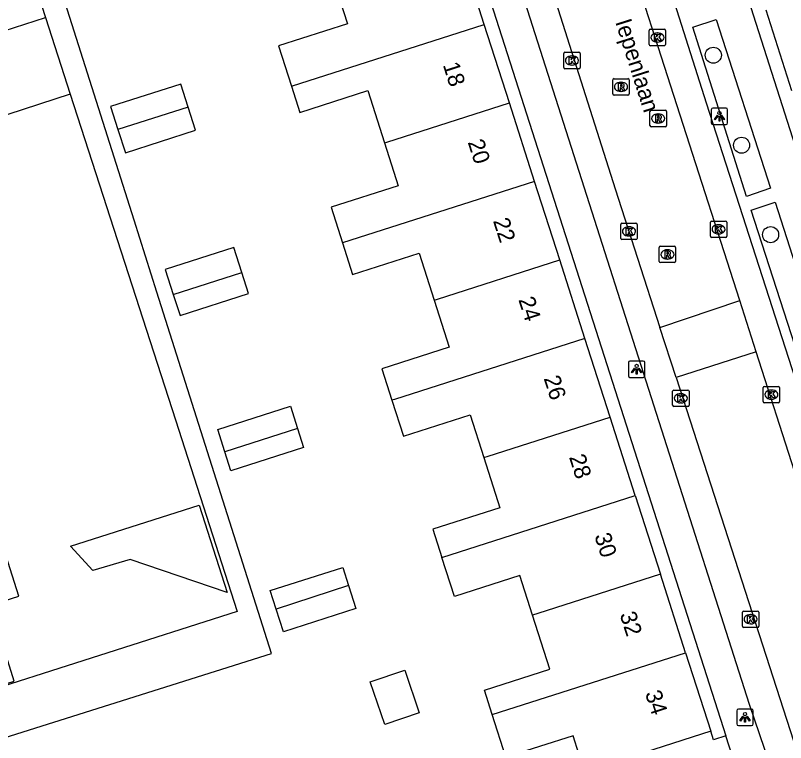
# Model space of a CAD drawing. Extents: x 159718 to 160783, y 383290 to 384030.
# Drawn here: x 160111.85 to 160158.8, y 383596.25 to 383640.55 of the extents above; entities that cross this region are included whole.
import ezdxf

# ---------------------------------------------------------------- set-up
doc = ezdxf.new("R2010")
doc.units = 0
for name, color, linetype in [('IMGEO_Boom', 7, 'Continuous'), ('IMGEO_Kolk', 7, 'Continuous'), ('IMGEO_Lichtpunt', 7, 'Continuous'), ('IMGEO_Openbare_ruimte_label', 7, 'Continuous'), ('IMGEO_Pand', 7, 'Continuous'), ('IMGEO_Pand_nummerreeks', 7, 'Continuous'), ('IMGEO_Rijbaan_lokaal_open', 7, 'Continuous'), ('IMGEO_Rioolput', 7, 'Continuous'), ('IMGEO_Voetpad_open', 7, 'Continuous')]:
    doc.layers.add(name, color=color, linetype=linetype)

msp = doc.modelspace()

# ---------------------------------------------------------------- linework, layer by layer
at = {"layer": 'IMGEO_Boom'}
for centre in [(160154.395, 383638.127), (160156.119, 383632.642), (160157.889, 383627.194)]:
    msp.add_circle(centre, 0.489, dxfattribs=at)
at = {"layer": 'IMGEO_Kolk'}
for p, q in [((160150.488, 383638.781), (160150.488, 383639.633)), ((160150.563, 383639.707), (160151.415, 383639.707)), ((160150.976, 383639.487), (160151.001, 383639.487)), ((160151.489, 383639.633), (160151.489, 383638.781)), ((160150.999, 383638.927), (160150.974, 383638.927)), ((160151.415, 383638.707), (160150.563, 383638.707)), ((160145.277, 383637.379), (160145.277, 383638.231)), ((160145.352, 383638.305), (160146.204, 383638.305)), ((160145.765, 383638.085), (160145.79, 383638.085)), ((160146.278, 383638.231), (160146.278, 383637.379)), ((160145.788, 383637.525), (160145.763, 383637.525)), ((160146.204, 383637.305), (160145.352, 383637.305)), ((160154.29, 383628.02), (160155.142, 383628.02)), ((160148.752, 383626.967), (160148.752, 383627.819)), ((160148.827, 383627.893), (160149.679, 383627.893)), ((160149.24, 383627.673), (160149.265, 383627.673)), ((160149.753, 383627.819), (160149.753, 383626.967)), ((160154.215, 383627.094), (160154.215, 383627.946)), ((160154.703, 383627.8), (160154.728, 383627.8)), ((160155.216, 383627.946), (160155.216, 383627.094)), ((160149.263, 383627.113), (160149.238, 383627.113)), ((160154.726, 383627.24), (160154.701, 383627.24)), ((160149.679, 383626.893), (160148.827, 383626.893)), ((160155.142, 383627.02), (160154.29, 383627.02)), ((160151.991, 383617.725), (160152.843, 383617.725)), ((160157.435, 383617.023), (160157.435, 383617.875)), ((160157.51, 383617.949), (160158.362, 383617.949)), ((160157.923, 383617.729), (160157.948, 383617.729)), ((160158.436, 383617.875), (160158.436, 383617.023)), ((160151.916, 383616.799), (160151.916, 383617.651)), ((160152.404, 383617.505), (160152.429, 383617.505)), ((160152.917, 383617.651), (160152.917, 383616.799)), ((160152.427, 383616.945), (160152.402, 383616.945)), ((160158.362, 383616.949), (160157.51, 383616.949)), ((160157.946, 383617.169), (160157.921, 383617.169)), ((160152.843, 383616.725), (160151.991, 383616.725)), ((160156.166, 383603.339), (160156.166, 383604.191)), ((160156.241, 383604.265), (160157.093, 383604.265)), ((160157.167, 383604.191), (160157.167, 383603.339)), ((160156.654, 383604.045), (160156.679, 383604.045)), ((160157.093, 383603.265), (160156.241, 383603.265)), ((160156.677, 383603.485), (160156.652, 383603.485))]:
    msp.add_line(p, q, dxfattribs=at)
for points in [[(160150.488, 383638.781), (160150.488, 383639.633)], [(160150.563, 383639.707), (160151.415, 383639.707)], [(160150.809, 383639.407), (160150.932, 383639.407), (160150.932, 383639.256), (160151.062, 383639.407), (160151.226, 383639.407), (160151.08, 383639.256), (160151.233, 383639.007), (160151.081, 383639.007), (160150.996, 383639.171), (160150.932, 383639.104), (160150.932, 383639.007), (160150.809, 383639.007), (160150.809, 383639.407)], [(160151.489, 383639.633), (160151.489, 383638.781)], [(160151.415, 383638.707), (160150.563, 383638.707)], [(160145.277, 383637.379), (160145.277, 383638.231)], [(160145.352, 383638.305), (160146.204, 383638.305)], [(160145.598, 383638.005), (160145.721, 383638.005), (160145.721, 383637.854), (160145.851, 383638.005), (160146.015, 383638.005), (160145.869, 383637.854), (160146.022, 383637.605), (160145.87, 383637.605), (160145.785, 383637.769), (160145.721, 383637.702), (160145.721, 383637.605), (160145.598, 383637.605), (160145.598, 383638.005)], [(160146.278, 383638.231), (160146.278, 383637.379)], [(160146.204, 383637.305), (160145.352, 383637.305)], [(160154.29, 383628.02), (160155.142, 383628.02)], [(160148.752, 383626.967), (160148.752, 383627.819)], [(160148.827, 383627.893), (160149.679, 383627.893)], [(160149.073, 383627.593), (160149.196, 383627.593), (160149.196, 383627.442), (160149.326, 383627.593), (160149.49, 383627.593), (160149.344, 383627.442), (160149.497, 383627.193), (160149.345, 383627.193), (160149.26, 383627.357), (160149.196, 383627.29), (160149.196, 383627.193), (160149.073, 383627.193), (160149.073, 383627.593)], [(160149.753, 383627.819), (160149.753, 383626.967)], [(160154.215, 383627.094), (160154.215, 383627.946)], [(160154.536, 383627.72), (160154.659, 383627.72), (160154.659, 383627.569), (160154.789, 383627.72), (160154.953, 383627.72), (160154.807, 383627.569), (160154.96, 383627.32), (160154.808, 383627.32), (160154.723, 383627.484), (160154.659, 383627.417), (160154.659, 383627.32), (160154.536, 383627.32), (160154.536, 383627.72)], [(160155.216, 383627.946), (160155.216, 383627.094)], [(160149.679, 383626.893), (160148.827, 383626.893)], [(160155.142, 383627.02), (160154.29, 383627.02)], [(160151.991, 383617.725), (160152.843, 383617.725)], [(160157.435, 383617.023), (160157.435, 383617.875)], [(160157.51, 383617.949), (160158.362, 383617.949)], [(160158.436, 383617.875), (160158.436, 383617.023)], [(160151.916, 383616.799), (160151.916, 383617.651)], [(160152.237, 383617.425), (160152.36, 383617.425), (160152.36, 383617.274), (160152.49, 383617.425), (160152.654, 383617.425), (160152.508, 383617.274), (160152.661, 383617.025), (160152.509, 383617.025), (160152.424, 383617.189), (160152.36, 383617.122), (160152.36, 383617.025), (160152.237, 383617.025), (160152.237, 383617.425)], [(160152.917, 383617.651), (160152.917, 383616.799)], [(160157.756, 383617.649), (160157.879, 383617.649), (160157.879, 383617.498), (160158.009, 383617.649), (160158.173, 383617.649), (160158.027, 383617.498), (160158.18, 383617.249), (160158.028, 383617.249), (160157.943, 383617.413), (160157.879, 383617.346), (160157.879, 383617.249), (160157.756, 383617.249), (160157.756, 383617.649)], [(160158.362, 383616.949), (160157.51, 383616.949)], [(160152.843, 383616.725), (160151.991, 383616.725)], [(160156.166, 383603.339), (160156.166, 383604.191)], [(160156.241, 383604.265), (160157.093, 383604.265)], [(160157.167, 383604.191), (160157.167, 383603.339)], [(160156.487, 383603.965), (160156.61, 383603.965), (160156.61, 383603.814), (160156.74, 383603.965), (160156.904, 383603.965), (160156.758, 383603.814), (160156.911, 383603.565), (160156.759, 383603.565), (160156.674, 383603.729), (160156.61, 383603.662), (160156.61, 383603.565), (160156.487, 383603.565), (160156.487, 383603.965)], [(160157.093, 383603.265), (160156.241, 383603.265)]]:
    msp.add_lwpolyline(points, dxfattribs=at)
for centre, start, end in [((160150.565, 383639.631), 91.552, 178.448), ((160150.565, 383639.631), 91.552, 178.448), ((160151.413, 383639.631), 1.552, 88.448), ((160151.413, 383639.631), 1.552, 88.448), ((160150.565, 383638.783), 181.552, 268.448), ((160150.565, 383638.783), 181.552, 268.448), ((160151.413, 383638.783), 271.552, 358.448), ((160151.413, 383638.783), 271.552, 358.448), ((160145.354, 383638.229), 91.552, 178.448), ((160145.354, 383638.229), 91.552, 178.448), ((160146.202, 383638.229), 1.552, 88.448), ((160146.202, 383638.229), 1.552, 88.448), ((160145.354, 383637.381), 181.552, 268.448), ((160145.354, 383637.381), 181.552, 268.448), ((160146.202, 383637.381), 271.552, 358.448), ((160146.202, 383637.381), 271.552, 358.448), ((160154.292, 383627.944), 91.552, 178.448), ((160154.292, 383627.944), 91.552, 178.448), ((160155.14, 383627.944), 1.552, 88.448), ((160155.14, 383627.944), 1.552, 88.448), ((160148.829, 383627.817), 91.552, 178.448), ((160148.829, 383627.817), 91.552, 178.448), ((160149.677, 383627.817), 1.552, 88.448), ((160149.677, 383627.817), 1.552, 88.448), ((160154.292, 383627.096), 181.552, 268.448), ((160154.292, 383627.096), 181.552, 268.448), ((160155.14, 383627.096), 271.552, 358.448), ((160155.14, 383627.096), 271.552, 358.448), ((160148.829, 383626.969), 181.552, 268.448), ((160148.829, 383626.969), 181.552, 268.448), ((160149.677, 383626.969), 271.552, 358.448), ((160149.677, 383626.969), 271.552, 358.448), ((160151.993, 383617.649), 91.552, 178.448), ((160151.993, 383617.649), 91.552, 178.448), ((160152.841, 383617.649), 1.552, 88.448), ((160152.841, 383617.649), 1.552, 88.448), ((160157.512, 383617.873), 91.552, 178.448), ((160157.512, 383617.873), 91.552, 178.448), ((160158.36, 383617.873), 1.552, 88.448), ((160158.36, 383617.873), 1.552, 88.448), ((160151.993, 383616.801), 181.552, 268.448), ((160151.993, 383616.801), 181.552, 268.448), ((160152.841, 383616.801), 271.552, 358.448), ((160152.841, 383616.801), 271.552, 358.448), ((160157.512, 383617.025), 181.552, 268.448), ((160157.512, 383617.025), 181.552, 268.448), ((160158.36, 383617.025), 271.552, 358.448), ((160158.36, 383617.025), 271.552, 358.448), ((160156.243, 383604.189), 91.552, 178.448), ((160156.243, 383604.189), 91.552, 178.448), ((160157.091, 383604.189), 1.552, 88.448), ((160157.091, 383604.189), 1.552, 88.448), ((160156.243, 383603.341), 181.552, 268.448), ((160156.243, 383603.341), 181.552, 268.448), ((160157.091, 383603.341), 271.552, 358.448), ((160157.091, 383603.341), 271.552, 358.448)]:
    msp.add_arc(centre, 0.0765, start, end, dxfattribs=at)
for centre, major_axis, ratio, start_param, end_param in [((160150.975, 383639.207), (-0.387, 0.002), 0.722429, 4.712389, 7.853982), ((160151, 383639.207), (-0.39, 0.002), 0.717154, 1.570796, 4.712389), ((160145.764, 383637.805), (-0.387, 0.002), 0.722429, 4.712389, 7.853982), ((160145.789, 383637.805), (-0.39, 0.002), 0.717154, 1.570796, 4.712389), ((160149.239, 383627.393), (-0.387, 0.002), 0.722429, 4.712389, 7.853982), ((160149.264, 383627.393), (-0.39, 0.002), 0.717154, 1.570796, 4.712389), ((160154.702, 383627.52), (-0.387, 0.002), 0.722429, 4.712389, 7.853982), ((160154.727, 383627.52), (-0.39, 0.002), 0.717154, 1.570796, 4.712389), ((160157.922, 383617.449), (-0.387, 0.002), 0.722429, 4.712389, 7.853982), ((160157.947, 383617.449), (-0.39, 0.002), 0.717154, 1.570796, 4.712389), ((160152.403, 383617.225), (-0.387, 0.002), 0.722429, 4.712389, 7.853982), ((160152.428, 383617.225), (-0.39, 0.002), 0.717154, 1.570796, 4.712389), ((160156.653, 383603.765), (-0.387, 0.002), 0.722429, 4.712389, 7.853982), ((160156.678, 383603.765), (-0.39, 0.002), 0.717154, 1.570796, 4.712389)]:
    msp.add_ellipse(centre, major_axis=major_axis, ratio=ratio, start_param=start_param, end_param=end_param, dxfattribs=at)
at = {"layer": 'IMGEO_Lichtpunt'}
for p, q in [((160154.27, 383634.807), (160154.27, 383634)), ((160154.27, 383634.807), (160154.27, 383634)), ((160155.172, 383634.902), (160154.364, 383634.902)), ((160155.172, 383634.902), (160154.364, 383634.902)), ((160155.266, 383634), (160155.266, 383634.807)), ((160155.266, 383634), (160155.266, 383634.807)), ((160154.364, 383633.906), (160155.172, 383633.906)), ((160154.364, 383633.906), (160155.172, 383633.906)), ((160149.222, 383619.401), (160149.222, 383618.594)), ((160149.222, 383619.401), (160149.222, 383618.594)), ((160150.124, 383619.496), (160149.316, 383619.496)), ((160150.124, 383619.496), (160149.316, 383619.496)), ((160150.218, 383618.594), (160150.218, 383619.401)), ((160150.218, 383618.594), (160150.218, 383619.401)), ((160149.316, 383618.5), (160150.124, 383618.5)), ((160149.316, 383618.5), (160150.124, 383618.5)), ((160155.829, 383598.19), (160155.829, 383597.383)), ((160155.829, 383598.19), (160155.829, 383597.383)), ((160156.731, 383598.285), (160155.923, 383598.285)), ((160156.731, 383598.285), (160155.923, 383598.285)), ((160156.825, 383597.383), (160156.825, 383598.19)), ((160156.825, 383597.383), (160156.825, 383598.19)), ((160155.923, 383597.289), (160156.731, 383597.289)), ((160155.923, 383597.289), (160156.731, 383597.289))]:
    msp.add_line(p, q, dxfattribs=at)
for points in [[(160154.644, 383634.471), (160154.683, 383634.443), (160154.495, 383634.181), (160154.457, 383634.208), (160154.644, 383634.471)], [(160154.746, 383634.423), (160154.793, 383634.423), (160154.793, 383634.101), (160154.746, 383634.101), (160154.746, 383634.423)], [(160154.856, 383634.443), (160154.894, 383634.47), (160155.081, 383634.208), (160155.042, 383634.18), (160154.856, 383634.443)], [(160149.596, 383619.065), (160149.635, 383619.037), (160149.447, 383618.775), (160149.409, 383618.802), (160149.596, 383619.065)], [(160149.698, 383619.017), (160149.745, 383619.017), (160149.745, 383618.695), (160149.698, 383618.695), (160149.698, 383619.017)], [(160149.808, 383619.037), (160149.846, 383619.064), (160150.033, 383618.802), (160149.994, 383618.774), (160149.808, 383619.037)], [(160156.203, 383597.854), (160156.242, 383597.826), (160156.054, 383597.564), (160156.016, 383597.591), (160156.203, 383597.854)], [(160156.305, 383597.806), (160156.352, 383597.806), (160156.352, 383597.484), (160156.305, 383597.484), (160156.305, 383597.806)], [(160156.415, 383597.826), (160156.453, 383597.853), (160156.64, 383597.591), (160156.601, 383597.563), (160156.415, 383597.826)]]:
    msp.add_lwpolyline(points, dxfattribs=at)
for centre in [(160154.769, 383634.605), (160149.721, 383619.199), (160156.328, 383597.988)]:
    msp.add_circle(centre, 0.0994, dxfattribs=at)
for centre, start, end in [((160154.364, 383634.807), 90, 180), ((160154.364, 383634.807), 90, 180), ((160155.172, 383634.807), 0, 90), ((160155.172, 383634.807), 0, 90), ((160154.364, 383634), 180, 270), ((160154.364, 383634), 180, 270), ((160155.172, 383634), 270, 0), ((160155.172, 383634), 270, 360), ((160149.316, 383619.401), 90, 180), ((160149.316, 383619.401), 90, 180), ((160150.124, 383619.401), 0, 90), ((160150.124, 383619.401), 0, 90), ((160149.316, 383618.594), 180, 270), ((160149.316, 383618.594), 180, 270), ((160150.124, 383618.594), 270, 0), ((160150.124, 383618.594), 270, 360), ((160155.923, 383598.19), 90, 180), ((160155.923, 383598.19), 90, 180), ((160156.731, 383598.19), 0, 90), ((160156.731, 383598.19), 0, 90), ((160155.923, 383597.383), 180, 270), ((160155.923, 383597.383), 180, 270), ((160156.731, 383597.383), 270, 0), ((160156.731, 383597.383), 270, 360)]:
    msp.add_arc(centre, 0.0946, start, end, dxfattribs=at)
at = {"layer": 'IMGEO_Pand'}
for points in [[(160140.434, 383640.007), (160138.9, 383644.792)], [(160131.338, 383642.375), (160132.087, 383640.033), (160127.896, 383638.693), (160128.678, 383636.249)], [(160157.593, 383640.887), (160159.161, 383635.985)], [(160115.198, 383635.752), (160111.389, 383634.522), (160109.879, 383639.2), (160113.688, 383640.429)], [(160113.688, 383640.429), (160115.198, 383635.752)], [(160128.678, 383636.249), (160140.434, 383640.007)], [(160141.968, 383635.222), (160140.434, 383640.007)], [(160122.383, 383634.962), (160121.933, 383636.367), (160117.653, 383634.998), (160118.103, 383633.592)], [(160128.678, 383636.249), (160129.19, 383634.645), (160133.334, 383635.97), (160134.352, 383632.786)], [(160134.352, 383632.786), (160134.496, 383632.832), (160141.968, 383635.222)], [(160143.503, 383630.436), (160141.968, 383635.222)], [(160122.383, 383634.962), (160118.103, 383633.592)], [(160118.103, 383633.592), (160118.553, 383632.187), (160122.833, 383633.556), (160122.383, 383634.962)], [(160134.352, 383632.786), (160135.186, 383630.177), (160131.09, 383628.868), (160131.786, 383626.691)], [(160143.503, 383630.436), (160131.786, 383626.691)], [(160145.037, 383625.651), (160143.503, 383630.436)], [(160131.786, 383626.691), (160132.399, 383624.771), (160136.455, 383626.068), (160137.371, 383623.2)], [(160125.652, 383624.888), (160125.166, 383626.409), (160120.99, 383625.074), (160121.476, 383623.553)], [(160137.371, 383623.2), (160137.577, 383623.266), (160145.037, 383625.651)], [(160146.571, 383620.865), (160145.037, 383625.651)], [(160121.476, 383623.553), (160125.652, 383624.888)], [(160121.476, 383623.553), (160121.887, 383622.269), (160126.063, 383623.604), (160125.652, 383624.888)], [(160137.371, 383623.2), (160138.288, 383620.331), (160134.194, 383619.023), (160134.807, 383617.104)], [(160146.571, 383620.865), (160134.958, 383617.153), (160134.807, 383617.104)], [(160148.105, 383616.08), (160146.571, 383620.865)], [(160124.62, 383613.969), (160124.186, 383615.324), (160128.612, 383616.74), (160129.043, 383615.393)], [(160134.807, 383617.104), (160135.509, 383614.908), (160139.583, 383616.21), (160140.412, 383613.62)], [(160140.412, 383613.62), (160140.661, 383613.7), (160148.105, 383616.08)], [(160149.639, 383611.295), (160148.105, 383616.08)], [(160129.043, 383615.393), (160129.417, 383614.224), (160124.991, 383612.807), (160124.62, 383613.969)], [(160129.043, 383615.393), (160124.62, 383613.969)], [(160140.412, 383613.62), (160141.391, 383610.559), (160137.3, 383609.25), (160137.851, 383607.526)], [(160137.851, 383607.526), (160149.639, 383611.295)], [(160149.639, 383611.295), (160151.174, 383606.509)], [(160123.06, 383610.716), (160124.76, 383605.386), (160118.85, 383607.395), (160116.565, 383606.734), (160115.208, 383608.212), (160123.06, 383610.716)], [(160108.575, 383598.879), (160108.547, 383598.968), (160111.782, 383600), (160110.311, 383604.614), (160112.063, 383605.173), (160111.27, 383607.66)], [(160143.379, 383604.016), (160142.609, 383606.426), (160138.611, 383605.148), (160137.851, 383607.526)], [(160127.74, 383604.388), (160127.381, 383605.509), (160131.806, 383606.925), (160132.163, 383605.812)], [(160151.174, 383606.509), (160143.696, 383604.117), (160143.379, 383604.016)], [(160152.708, 383601.723), (160151.174, 383606.509)], [(160132.163, 383605.812), (160132.612, 383604.409), (160128.186, 383602.993), (160127.74, 383604.388)], [(160132.163, 383605.812), (160127.74, 383604.388)], [(160140.922, 383597.955), (160140.443, 383599.451), (160144.431, 383600.727), (160143.379, 383604.016)], [(160140.922, 383597.955), (160152.708, 383601.723)], [(160152.708, 383601.723), (160154.243, 383596.937)], [(160135.586, 383600.669), (160136.466, 383598.072), (160134.364, 383597.36), (160133.484, 383599.957), (160135.586, 383600.669)], [(160146.54, 383594.474), (160145.842, 383596.66), (160141.753, 383595.354), (160140.922, 383597.955)], [(160154.243, 383596.937), (160146.728, 383594.535), (160146.54, 383594.474)], [(160155.168, 383596.67), (160154.406, 383596.427), (160154.243, 383596.937)], [(160156.559, 383592.314), (160155.168, 383596.67)]]:
    msp.add_lwpolyline(points, dxfattribs=at)
at = {"layer": 'IMGEO_Rijbaan_lokaal_open'}
for points in [[(160156.009, 383623.174), (160141.47, 383668.37)], [(160143.499, 383668.167), (160153.963, 383635.229), (160166.59, 383596.057)], [(160169.432, 383601.256), (160149.063, 383664.924)], [(160141.576, 383651.473), (160148.415, 383629.989), (160151.141, 383621.545)], [(160156.427, 383629.528), (160153.142, 383639.825), (160154.578, 383640.311), (160157.887, 383630.032), (160156.427, 383629.528)], [(160161.486, 383618.854), (160160.025, 383618.383), (160156.7, 383628.678), (160158.161, 383629.183), (160161.486, 383618.854)], [(160151.141, 383621.545), (160156.009, 383623.174)], [(160157.01, 383620.063), (160156.009, 383623.174)], [(160152.126, 383618.495), (160151.141, 383621.545)], [(160157.01, 383620.063), (160152.126, 383618.495)], [(160165.063, 383594.734), (160160.958, 383607.539), (160159.349, 383612.791), (160157.01, 383620.063)], [(160152.126, 383618.495), (160160.33, 383593.082)]]:
    msp.add_lwpolyline(points, dxfattribs=at)
at = {"layer": 'IMGEO_Rioolput'}
for p, q in [((160148.267, 383635.771), (160148.267, 383636.623)), ((160148.342, 383636.697), (160149.194, 383636.697)), ((160148.755, 383636.477), (160148.78, 383636.477)), ((160149.268, 383636.623), (160149.268, 383635.771)), ((160149.194, 383635.697), (160148.342, 383635.697)), ((160148.778, 383635.917), (160148.753, 383635.917)), ((160150.534, 383633.845), (160150.534, 383634.697)), ((160150.609, 383634.771), (160151.461, 383634.771)), ((160151.535, 383634.697), (160151.535, 383633.845)), ((160151.022, 383634.551), (160151.047, 383634.551)), ((160151.461, 383633.771), (160150.609, 383633.771)), ((160151.045, 383633.991), (160151.02, 383633.991)), ((160151.097, 383625.564), (160151.097, 383626.416)), ((160151.172, 383626.49), (160152.024, 383626.49)), ((160151.585, 383626.27), (160151.61, 383626.27)), ((160152.098, 383626.416), (160152.098, 383625.564)), ((160151.608, 383625.71), (160151.583, 383625.71)), ((160152.024, 383625.49), (160151.172, 383625.49))]:
    msp.add_line(p, q, dxfattribs=at)
for points in [[(160148.267, 383635.771), (160148.267, 383636.623)], [(160148.342, 383636.697), (160149.194, 383636.697)], [(160149.268, 383636.623), (160149.268, 383635.771)], [(160148.856, 383636.395), (160148.604, 383636.397), (160148.604, 383635.997)], [(160148.604, 383635.997), (160148.728, 383635.997), (160148.728, 383636.159), (160148.739, 383636.159)], [(160148.782, 383636.316), (160148.728, 383636.316), (160148.728, 383636.235)], [(160148.728, 383636.235), (160148.78, 383636.235)], [(160148.786, 383636.13), (160148.857, 383635.997), (160148.997, 383635.997), (160148.932, 383636.123)], [(160149.194, 383635.697), (160148.342, 383635.697)], [(160150.534, 383633.845), (160150.534, 383634.697)], [(160150.609, 383634.771), (160151.461, 383634.771)], [(160151.535, 383634.697), (160151.535, 383633.845)], [(160151.123, 383634.469), (160150.871, 383634.471), (160150.871, 383634.071)], [(160150.871, 383634.071), (160150.995, 383634.071), (160150.995, 383634.233), (160151.006, 383634.233)], [(160151.049, 383634.39), (160150.995, 383634.39), (160150.995, 383634.309)], [(160150.995, 383634.309), (160151.047, 383634.309)], [(160151.053, 383634.204), (160151.124, 383634.071), (160151.264, 383634.071), (160151.199, 383634.197)], [(160151.461, 383633.771), (160150.609, 383633.771)], [(160151.097, 383625.564), (160151.097, 383626.416)], [(160151.172, 383626.49), (160152.024, 383626.49)], [(160151.686, 383626.188), (160151.434, 383626.19), (160151.434, 383625.79)], [(160152.098, 383626.416), (160152.098, 383625.564)], [(160151.434, 383625.79), (160151.558, 383625.79), (160151.558, 383625.952), (160151.569, 383625.952)], [(160151.612, 383626.109), (160151.558, 383626.109), (160151.558, 383626.028)], [(160151.558, 383626.028), (160151.61, 383626.028)], [(160151.616, 383625.923), (160151.687, 383625.79), (160151.827, 383625.79), (160151.762, 383625.916)], [(160152.024, 383625.49), (160151.172, 383625.49)]]:
    msp.add_lwpolyline(points, dxfattribs=at)
for centre, radius, start, end in [((160148.344, 383636.621), 0.0765, 91.552, 178.448), ((160148.344, 383636.621), 0.0765, 91.552, 178.448), ((160149.192, 383636.621), 0.0765, 1.552, 88.448), ((160149.192, 383636.621), 0.0765, 1.552, 88.448), ((160148.738, 383636.106), 0.0533, 26.0293, 88.6989), ((160148.764, 383636.424), 0.19, 274.7715, 282.9687), ((160148.788, 383636.22), 0.0964, 77.0061, 93.1865), ((160148.802, 383636.277), 0.0378, 276.6634, 79.6772), ((160148.855, 383636.285), 0.109, 350.3612, 89.416), ((160148.853, 383636.285), 0.112, 277.5842, 350.9817), ((160148.837, 383636.07), 0.108, 29.5134, 73.7905), ((160148.344, 383635.773), 0.0765, 181.552, 268.448), ((160148.344, 383635.773), 0.0765, 181.552, 268.448), ((160149.192, 383635.773), 0.0765, 271.552, 358.448), ((160149.192, 383635.773), 0.0765, 271.552, 358.448), ((160150.611, 383634.695), 0.0765, 91.552, 178.448), ((160150.611, 383634.695), 0.0765, 91.552, 178.448), ((160151.459, 383634.695), 0.0765, 1.552, 88.448), ((160151.459, 383634.695), 0.0765, 1.552, 88.448), ((160151.005, 383634.18), 0.0533, 26.0293, 88.6989), ((160151.031, 383634.498), 0.19, 274.7715, 282.9687), ((160151.055, 383634.294), 0.0964, 77.0061, 93.1865), ((160151.069, 383634.351), 0.0378, 276.6634, 79.6772), ((160151.122, 383634.359), 0.109, 350.3612, 89.416), ((160151.12, 383634.359), 0.112, 277.5842, 350.9817), ((160151.104, 383634.144), 0.108, 29.5134, 73.7905), ((160150.611, 383633.847), 0.0765, 181.552, 268.448), ((160150.611, 383633.847), 0.0765, 181.552, 268.448), ((160151.459, 383633.847), 0.0765, 271.552, 358.448), ((160151.459, 383633.847), 0.0765, 271.552, 358.448), ((160151.174, 383626.414), 0.0765, 91.552, 178.448), ((160151.174, 383626.414), 0.0765, 91.552, 178.448), ((160151.685, 383626.078), 0.109, 350.3612, 89.416), ((160152.022, 383626.414), 0.0765, 1.552, 88.448), ((160152.022, 383626.414), 0.0765, 1.552, 88.448), ((160151.568, 383625.899), 0.0533, 26.0293, 88.6989), ((160151.594, 383626.217), 0.19, 274.7715, 282.9687), ((160151.618, 383626.013), 0.0964, 77.0061, 93.1865), ((160151.632, 383626.07), 0.0378, 276.6634, 79.6772), ((160151.683, 383626.078), 0.112, 277.5842, 350.9817), ((160151.667, 383625.863), 0.108, 29.5134, 73.7905), ((160151.174, 383625.566), 0.0765, 181.552, 268.448), ((160151.174, 383625.566), 0.0765, 181.552, 268.448), ((160152.022, 383625.566), 0.0765, 271.552, 358.448), ((160152.022, 383625.566), 0.0765, 271.552, 358.448)]:
    msp.add_arc(centre, radius, start, end, dxfattribs=at)
for centre, major_axis, ratio, start_param, end_param in [((160148.754, 383636.197), (-0.387, 0.002), 0.722429, 4.712389, 7.853982), ((160148.779, 383636.197), (-0.39, 0.002), 0.717154, 1.570796, 4.712389), ((160151.021, 383634.271), (-0.387, 0.002), 0.722429, 4.712389, 7.853982), ((160151.046, 383634.271), (-0.39, 0.002), 0.717154, 1.570796, 4.712389), ((160151.584, 383625.99), (-0.387, 0.002), 0.722429, 4.712389, 7.853982), ((160151.609, 383625.99), (-0.39, 0.002), 0.717154, 1.570796, 4.712389)]:
    msp.add_ellipse(centre, major_axis=major_axis, ratio=ratio, start_param=start_param, end_param=end_param, dxfattribs=at)
at = {"layer": 'IMGEO_Voetpad_open'}
for points in [[(160158.444, 383593.145), (160156.603, 383598.576), (160140.081, 383650.261)], [(160104.211, 383594.364), (160110.764, 383596.41), (160127.456, 383601.679), (160120.476, 383623.696), (160119.09, 383628.068), (160113.81, 383644.725), (160123.842, 383647.93)], [(160110.921, 383645.315), (160111.509, 383645.501), (160112.28, 383643.114), (160112.77, 383643.272), (160113.688, 383640.429)], [(160139.479, 383645.604), (160155.168, 383596.67)], [(160115.198, 383635.752), (160121.604, 383615.913), (160125.373, 383604.243), (160108.575, 383598.879)]]:
    msp.add_lwpolyline(points, dxfattribs=at)

# ---------------------------------------------------------------- texts
at = {"layer": 'IMGEO_Openbare_ruimte_label'}
msp.add_text('Iepenlaan', height=1, rotation=287.5831, dxfattribs=at).set_placement((160148.408, 383640.16))
at = {"layer": 'IMGEO_Pand_nummerreeks'}
for s, p in [('18', (160137.899, 383637.539)), ('20', (160139.415, 383632.83)), ('22', (160140.957, 383628.04)), ('24', (160142.502, 383623.241)), ('26', (160144.046, 383618.445)), ('28', (160145.591, 383613.646)), ('30', (160147.135, 383608.85)), ('32', (160148.677, 383604.059)), ('34', (160150.222, 383599.26))]:
    msp.add_text(s, height=1, rotation=287.8474, dxfattribs=at).set_placement(p)

doc.saveas('drawing.dxf')
